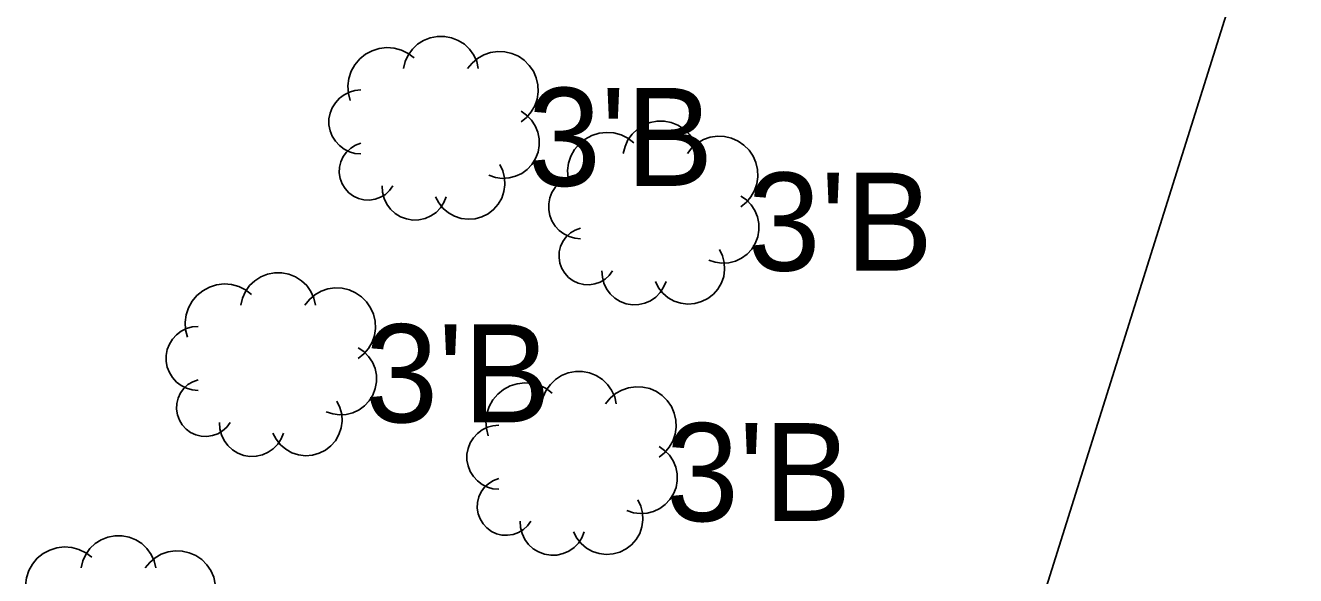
# Model space of a CAD drawing. Extents: x 1363693 to 1365209, y 422201 to 424153.
# Drawn here: x 1364173.2 to 1364193.92, y 423011.13 to 423020.1 of the extents above; entities that cross this region are included whole.
import ezdxf

# ---------------------------------------------------------------- set-up
doc = ezdxf.new("R2010")
doc.units = 0
for name, color, linetype in [('VG_X_Cells', 7, 'Continuous'), ('VG_X_Flower_Bed', 7, 'Continuous'), ('VG_X_Text', 7, 'Continuous')]:
    doc.layers.add(name, color=color, linetype=linetype)

msp = doc.modelspace()

# ---------------------------------------------------------------- linework, layer by layer
at = {"layer": 'VG_X_Cells'}
for points in [[(1364180.586, 423019.399), (1364180.559, 423019.513), (1364180.51, 423019.62), (1364180.442, 423019.715), (1364180.358, 423019.796), (1364180.259, 423019.859), (1364180.15, 423019.903), (1364180.035, 423019.925), (1364179.918, 423019.925), (1364179.803, 423019.903), (1364179.694, 423019.859), (1364179.596, 423019.796), (1364179.511, 423019.715), (1364179.443, 423019.62), (1364179.395, 423019.513), (1364179.367, 423019.399)], [(1364179.541, 423019.573), (1364179.443, 423019.647), (1364179.333, 423019.701), (1364179.215, 423019.733), (1364179.093, 423019.742), (1364178.971, 423019.728), (1364178.855, 423019.691), (1364178.747, 423019.633), (1364178.652, 423019.556), (1364178.573, 423019.462), (1364178.513, 423019.355), (1364178.475, 423019.239), (1364178.459, 423019.118), (1364178.466, 423018.995), (1364178.496, 423018.877)], [(1364181.283, 423018.529), (1364181.374, 423018.602), (1364181.449, 423018.691), (1364181.507, 423018.792), (1364181.545, 423018.903), (1364181.562, 423019.018), (1364181.557, 423019.135), (1364181.531, 423019.249), (1364181.484, 423019.355), (1364181.418, 423019.452), (1364181.335, 423019.534), (1364181.239, 423019.6), (1364181.132, 423019.647), (1364181.018, 423019.673), (1364180.902, 423019.678), (1364180.786, 423019.661), (1364180.676, 423019.623), (1364180.575, 423019.565), (1364180.486, 423019.49), (1364180.412, 423019.399)], [(1364178.671, 423019.051), (1364178.574, 423019.042), (1364178.482, 423019.016), (1364178.395, 423018.973), (1364178.319, 423018.915), (1364178.254, 423018.843), (1364178.203, 423018.761), (1364178.168, 423018.671), (1364178.15, 423018.577), (1364178.15, 423018.48), (1364178.168, 423018.386), (1364178.203, 423018.296), (1364178.254, 423018.214), (1364178.319, 423018.142), (1364178.395, 423018.084), (1364178.482, 423018.041), (1364178.574, 423018.015), (1364178.671, 423018.006)], [(1364180.76, 423017.658), (1364180.866, 423017.623), (1364180.976, 423017.608), (1364181.087, 423017.615), (1364181.195, 423017.642), (1364181.295, 423017.69), (1364181.385, 423017.755), (1364181.461, 423017.837), (1364181.52, 423017.931), (1364181.56, 423018.035), (1364181.58, 423018.144), (1364181.578, 423018.255), (1364181.556, 423018.364), (1364181.513, 423018.467), (1364181.452, 423018.56), (1364181.374, 423018.639), (1364181.283, 423018.703)], [(1364184.17, 423018.016), (1364184.143, 423018.13), (1364184.094, 423018.237), (1364184.026, 423018.332), (1364183.942, 423018.413), (1364183.843, 423018.476), (1364183.734, 423018.52), (1364183.619, 423018.542), (1364183.502, 423018.542), (1364183.387, 423018.52), (1364183.278, 423018.476), (1364183.18, 423018.413), (1364183.095, 423018.332), (1364183.027, 423018.237), (1364182.979, 423018.13), (1364182.951, 423018.016)], [(1364178.671, 423018.18), (1364178.584, 423018.148), (1364178.505, 423018.101), (1364178.437, 423018.038), (1364178.383, 423017.964), (1364178.344, 423017.88), (1364178.322, 423017.791), (1364178.318, 423017.698), (1364178.332, 423017.607), (1364178.364, 423017.521), (1364178.412, 423017.442), (1364178.474, 423017.374), (1364178.548, 423017.319), (1364178.632, 423017.28), (1364178.721, 423017.258), (1364178.813, 423017.254), (1364178.905, 423017.268), (1364178.991, 423017.299), (1364179.07, 423017.347), (1364179.138, 423017.409), (1364179.193, 423017.484)], [(1364183.125, 423018.19), (1364183.027, 423018.264), (1364182.917, 423018.318), (1364182.799, 423018.35), (1364182.677, 423018.359), (1364182.555, 423018.345), (1364182.439, 423018.308), (1364182.331, 423018.25), (1364182.236, 423018.173), (1364182.157, 423018.079), (1364182.097, 423017.972), (1364182.059, 423017.856), (1364182.043, 423017.735), (1364182.05, 423017.612), (1364182.08, 423017.494)], [(1364184.867, 423017.146), (1364184.958, 423017.219), (1364185.033, 423017.308), (1364185.091, 423017.409), (1364185.129, 423017.52), (1364185.146, 423017.635), (1364185.141, 423017.752), (1364185.115, 423017.866), (1364185.068, 423017.972), (1364185.002, 423018.069), (1364184.919, 423018.151), (1364184.823, 423018.217), (1364184.716, 423018.264), (1364184.602, 423018.29), (1364184.486, 423018.295), (1364184.37, 423018.278), (1364184.26, 423018.24), (1364184.159, 423018.182), (1364184.07, 423018.107), (1364183.996, 423018.016)], [(1364179.89, 423017.309), (1364179.942, 423017.208), (1364180.013, 423017.119), (1364180.1, 423017.045), (1364180.199, 423016.99), (1364180.307, 423016.955), (1364180.421, 423016.941), (1364180.534, 423016.95), (1364180.644, 423016.98), (1364180.746, 423017.031), (1364180.836, 423017.1), (1364180.911, 423017.186), (1364180.968, 423017.285), (1364181.004, 423017.393), (1364181.02, 423017.505), (1364181.013, 423017.619), (1364180.984, 423017.729), (1364180.935, 423017.832)], [(1364182.255, 423017.668), (1364182.158, 423017.659), (1364182.066, 423017.633), (1364181.979, 423017.59), (1364181.903, 423017.532), (1364181.838, 423017.46), (1364181.787, 423017.378), (1364181.752, 423017.288), (1364181.734, 423017.194), (1364181.734, 423017.097), (1364181.752, 423017.003), (1364181.787, 423016.913), (1364181.838, 423016.831), (1364181.903, 423016.759), (1364181.979, 423016.701), (1364182.066, 423016.658), (1364182.158, 423016.632), (1364182.255, 423016.623)], [(1364179.019, 423017.484), (1364179.025, 423017.381), (1364179.05, 423017.281), (1364179.094, 423017.188), (1364179.155, 423017.106), (1364179.23, 423017.036), (1364179.318, 423016.982), (1364179.414, 423016.946), (1364179.516, 423016.929), (1364179.618, 423016.932), (1364179.719, 423016.955), (1364179.813, 423016.996), (1364179.897, 423017.054), (1364179.969, 423017.128), (1364180.025, 423017.214), (1364180.064, 423017.309)], [(1364184.344, 423016.275), (1364184.45, 423016.24), (1364184.56, 423016.225), (1364184.671, 423016.232), (1364184.779, 423016.259), (1364184.879, 423016.307), (1364184.969, 423016.372), (1364185.045, 423016.454), (1364185.104, 423016.548), (1364185.144, 423016.652), (1364185.164, 423016.761), (1364185.162, 423016.872), (1364185.14, 423016.981), (1364185.097, 423017.084), (1364185.036, 423017.177), (1364184.958, 423017.256), (1364184.867, 423017.32)], [(1364182.255, 423016.797), (1364182.168, 423016.765), (1364182.089, 423016.718), (1364182.021, 423016.655), (1364181.967, 423016.581), (1364181.928, 423016.497), (1364181.906, 423016.408), (1364181.902, 423016.315), (1364181.916, 423016.224), (1364181.948, 423016.138), (1364181.996, 423016.059), (1364182.058, 423015.991), (1364182.132, 423015.936), (1364182.216, 423015.897), (1364182.305, 423015.875), (1364182.397, 423015.871), (1364182.489, 423015.885), (1364182.575, 423015.916), (1364182.654, 423015.964), (1364182.722, 423016.026), (1364182.777, 423016.101)], [(1364183.474, 423015.926), (1364183.526, 423015.825), (1364183.597, 423015.736), (1364183.684, 423015.662), (1364183.783, 423015.607), (1364183.891, 423015.572), (1364184.005, 423015.558), (1364184.118, 423015.567), (1364184.228, 423015.597), (1364184.33, 423015.648), (1364184.42, 423015.717), (1364184.495, 423015.803), (1364184.552, 423015.902), (1364184.588, 423016.01), (1364184.604, 423016.122), (1364184.597, 423016.236), (1364184.568, 423016.346), (1364184.519, 423016.449)], [(1364182.603, 423016.101), (1364182.609, 423015.998), (1364182.634, 423015.898), (1364182.678, 423015.805), (1364182.739, 423015.723), (1364182.814, 423015.653), (1364182.902, 423015.599), (1364182.998, 423015.563), (1364183.1, 423015.546), (1364183.202, 423015.549), (1364183.303, 423015.572), (1364183.397, 423015.613), (1364183.481, 423015.671), (1364183.553, 423015.745), (1364183.609, 423015.831), (1364183.648, 423015.926)], [(1364176.886, 423015.716), (1364176.788, 423015.79), (1364176.678, 423015.844), (1364176.56, 423015.876), (1364176.438, 423015.885), (1364176.316, 423015.871), (1364176.2, 423015.834), (1364176.092, 423015.776), (1364175.997, 423015.699), (1364175.918, 423015.605), (1364175.858, 423015.498), (1364175.82, 423015.382), (1364175.804, 423015.261), (1364175.811, 423015.138), (1364175.841, 423015.02)], [(1364177.931, 423015.542), (1364177.904, 423015.656), (1364177.855, 423015.763), (1364177.787, 423015.858), (1364177.703, 423015.939), (1364177.604, 423016.002), (1364177.495, 423016.046), (1364177.38, 423016.068), (1364177.263, 423016.068), (1364177.148, 423016.046), (1364177.039, 423016.002), (1364176.941, 423015.939), (1364176.856, 423015.858), (1364176.788, 423015.763), (1364176.74, 423015.656), (1364176.712, 423015.542)], [(1364178.628, 423014.672), (1364178.719, 423014.745), (1364178.794, 423014.834), (1364178.852, 423014.935), (1364178.89, 423015.046), (1364178.907, 423015.161), (1364178.902, 423015.278), (1364178.876, 423015.392), (1364178.829, 423015.498), (1364178.763, 423015.595), (1364178.68, 423015.677), (1364178.584, 423015.743), (1364178.477, 423015.79), (1364178.363, 423015.816), (1364178.247, 423015.821), (1364178.131, 423015.804), (1364178.021, 423015.766), (1364177.92, 423015.708), (1364177.831, 423015.633), (1364177.757, 423015.542)], [(1364176.016, 423015.194), (1364175.919, 423015.185), (1364175.827, 423015.159), (1364175.74, 423015.116), (1364175.664, 423015.058), (1364175.599, 423014.986), (1364175.548, 423014.904), (1364175.513, 423014.814), (1364175.495, 423014.72), (1364175.495, 423014.623), (1364175.513, 423014.529), (1364175.548, 423014.439), (1364175.599, 423014.357), (1364175.664, 423014.285), (1364175.74, 423014.227), (1364175.827, 423014.184), (1364175.919, 423014.158), (1364176.016, 423014.149)], [(1364178.105, 423013.801), (1364178.211, 423013.766), (1364178.321, 423013.751), (1364178.432, 423013.758), (1364178.54, 423013.785), (1364178.64, 423013.833), (1364178.73, 423013.898), (1364178.806, 423013.98), (1364178.865, 423014.074), (1364178.905, 423014.178), (1364178.925, 423014.287), (1364178.923, 423014.398), (1364178.901, 423014.507), (1364178.858, 423014.61), (1364178.797, 423014.703), (1364178.719, 423014.782), (1364178.628, 423014.846)], [(1364182.837, 423013.93), (1364182.81, 423014.044), (1364182.761, 423014.151), (1364182.693, 423014.246), (1364182.609, 423014.327), (1364182.51, 423014.39), (1364182.401, 423014.434), (1364182.286, 423014.456), (1364182.169, 423014.456), (1364182.054, 423014.434), (1364181.945, 423014.39), (1364181.847, 423014.327), (1364181.762, 423014.246), (1364181.694, 423014.151), (1364181.646, 423014.044), (1364181.618, 423013.93)], [(1364176.016, 423014.323), (1364175.929, 423014.291), (1364175.85, 423014.244), (1364175.782, 423014.181), (1364175.728, 423014.107), (1364175.689, 423014.023), (1364175.667, 423013.934), (1364175.663, 423013.841), (1364175.677, 423013.75), (1364175.709, 423013.664), (1364175.757, 423013.585), (1364175.819, 423013.517), (1364175.893, 423013.462), (1364175.977, 423013.423), (1364176.066, 423013.401), (1364176.158, 423013.397), (1364176.25, 423013.411), (1364176.336, 423013.442), (1364176.415, 423013.49), (1364176.483, 423013.552), (1364176.538, 423013.627)], [(1364181.792, 423014.104), (1364181.694, 423014.178), (1364181.584, 423014.232), (1364181.466, 423014.264), (1364181.344, 423014.273), (1364181.222, 423014.259), (1364181.106, 423014.222), (1364180.998, 423014.164), (1364180.903, 423014.087), (1364180.824, 423013.993), (1364180.764, 423013.886), (1364180.726, 423013.77), (1364180.71, 423013.649), (1364180.717, 423013.526), (1364180.747, 423013.408)], [(1364183.534, 423013.06), (1364183.625, 423013.133), (1364183.7, 423013.222), (1364183.758, 423013.323), (1364183.796, 423013.434), (1364183.813, 423013.549), (1364183.808, 423013.666), (1364183.782, 423013.78), (1364183.735, 423013.886), (1364183.669, 423013.983), (1364183.586, 423014.065), (1364183.49, 423014.131), (1364183.383, 423014.178), (1364183.269, 423014.204), (1364183.153, 423014.209), (1364183.037, 423014.192), (1364182.927, 423014.154), (1364182.826, 423014.096), (1364182.737, 423014.021), (1364182.663, 423013.93)], [(1364177.235, 423013.452), (1364177.287, 423013.351), (1364177.358, 423013.262), (1364177.445, 423013.188), (1364177.544, 423013.133), (1364177.652, 423013.098), (1364177.766, 423013.084), (1364177.879, 423013.093), (1364177.989, 423013.123), (1364178.091, 423013.174), (1364178.181, 423013.243), (1364178.256, 423013.329), (1364178.313, 423013.428), (1364178.349, 423013.536), (1364178.365, 423013.648), (1364178.358, 423013.762), (1364178.329, 423013.872), (1364178.28, 423013.975)], [(1364176.364, 423013.627), (1364176.37, 423013.524), (1364176.395, 423013.424), (1364176.439, 423013.331), (1364176.5, 423013.249), (1364176.575, 423013.179), (1364176.663, 423013.125), (1364176.759, 423013.089), (1364176.861, 423013.072), (1364176.963, 423013.075), (1364177.064, 423013.098), (1364177.158, 423013.139), (1364177.242, 423013.197), (1364177.314, 423013.271), (1364177.37, 423013.357), (1364177.409, 423013.452)], [(1364180.922, 423013.582), (1364180.825, 423013.573), (1364180.733, 423013.547), (1364180.646, 423013.504), (1364180.57, 423013.446), (1364180.505, 423013.374), (1364180.454, 423013.292), (1364180.419, 423013.202), (1364180.401, 423013.108), (1364180.401, 423013.011), (1364180.419, 423012.917), (1364180.454, 423012.827), (1364180.505, 423012.745), (1364180.57, 423012.673), (1364180.646, 423012.615), (1364180.733, 423012.572), (1364180.825, 423012.546), (1364180.922, 423012.537)], [(1364183.011, 423012.189), (1364183.117, 423012.154), (1364183.227, 423012.139), (1364183.338, 423012.146), (1364183.446, 423012.173), (1364183.546, 423012.221), (1364183.636, 423012.286), (1364183.712, 423012.368), (1364183.771, 423012.462), (1364183.811, 423012.566), (1364183.831, 423012.675), (1364183.829, 423012.786), (1364183.807, 423012.895), (1364183.764, 423012.998), (1364183.703, 423013.091), (1364183.625, 423013.17), (1364183.534, 423013.234)], [(1364180.922, 423012.711), (1364180.835, 423012.679), (1364180.756, 423012.632), (1364180.688, 423012.569), (1364180.634, 423012.495), (1364180.595, 423012.411), (1364180.573, 423012.322), (1364180.569, 423012.229), (1364180.583, 423012.138), (1364180.615, 423012.052), (1364180.663, 423011.973), (1364180.725, 423011.905), (1364180.799, 423011.85), (1364180.883, 423011.811), (1364180.972, 423011.789), (1364181.064, 423011.785), (1364181.156, 423011.799), (1364181.242, 423011.83), (1364181.321, 423011.878), (1364181.389, 423011.94), (1364181.444, 423012.015)], [(1364182.141, 423011.84), (1364182.193, 423011.739), (1364182.264, 423011.65), (1364182.351, 423011.576), (1364182.45, 423011.521), (1364182.558, 423011.486), (1364182.672, 423011.472), (1364182.785, 423011.481), (1364182.895, 423011.511), (1364182.997, 423011.562), (1364183.087, 423011.631), (1364183.162, 423011.717), (1364183.219, 423011.816), (1364183.255, 423011.924), (1364183.271, 423012.036), (1364183.264, 423012.15), (1364183.235, 423012.26), (1364183.186, 423012.363)], [(1364181.27, 423012.015), (1364181.276, 423011.912), (1364181.301, 423011.812), (1364181.345, 423011.719), (1364181.406, 423011.637), (1364181.481, 423011.567), (1364181.569, 423011.513), (1364181.665, 423011.477), (1364181.767, 423011.46), (1364181.869, 423011.463), (1364181.97, 423011.486), (1364182.064, 423011.527), (1364182.148, 423011.585), (1364182.22, 423011.659), (1364182.276, 423011.745), (1364182.315, 423011.84)], [(1364175.325, 423011.253), (1364175.298, 423011.367), (1364175.249, 423011.474), (1364175.181, 423011.569), (1364175.097, 423011.65), (1364174.998, 423011.713), (1364174.889, 423011.757), (1364174.774, 423011.779), (1364174.657, 423011.779), (1364174.542, 423011.757), (1364174.433, 423011.713), (1364174.335, 423011.65), (1364174.25, 423011.569), (1364174.182, 423011.474), (1364174.134, 423011.367), (1364174.106, 423011.253)], [(1364174.28, 423011.427), (1364174.182, 423011.501), (1364174.072, 423011.555), (1364173.954, 423011.587), (1364173.832, 423011.596), (1364173.71, 423011.582), (1364173.594, 423011.545), (1364173.486, 423011.487), (1364173.391, 423011.41), (1364173.312, 423011.316), (1364173.252, 423011.209), (1364173.214, 423011.093), (1364173.198, 423010.972), (1364173.205, 423010.849), (1364173.235, 423010.731)], [(1364176.022, 423010.383), (1364176.113, 423010.456), (1364176.188, 423010.545), (1364176.246, 423010.646), (1364176.284, 423010.757), (1364176.301, 423010.872), (1364176.296, 423010.989), (1364176.27, 423011.103), (1364176.223, 423011.209), (1364176.157, 423011.306), (1364176.074, 423011.388), (1364175.978, 423011.454), (1364175.871, 423011.501), (1364175.757, 423011.527), (1364175.641, 423011.532), (1364175.525, 423011.515), (1364175.415, 423011.477), (1364175.314, 423011.419), (1364175.225, 423011.344), (1364175.151, 423011.253)]]:
    msp.add_lwpolyline(points, dxfattribs=at)
at = {"layer": 'VG_X_Flower_Bed'}
msp.add_line((1364187.138, 423002.302), (1364193.968, 423024.045), dxfattribs=at)

# ---------------------------------------------------------------- texts
at = {"layer": 'VG_X_Text'}
for p in [(1364181.394, 423017.485), (1364184.978, 423016.102), (1364178.739, 423013.628), (1364183.645, 423012.016)]:
    msp.add_text("3'B", height=1.6, dxfattribs=at).set_placement(p)

doc.saveas('drawing.dxf')
